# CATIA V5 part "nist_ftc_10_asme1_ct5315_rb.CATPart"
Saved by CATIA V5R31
Part number: nist_ftc_10_asme1
Nomenclature: nist_ftc_10_asme1
Source: Unknown
Bounding box of the stored display mesh (mm): x -79 to 79, y 0 to 31, z -37.5 to 37.5
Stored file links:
  E:\users\dgn\TPS V5\Import-export annotations\Step\PMI representation 2015\NIST UC\FTC\nist_ftc_10_asme1_ct5315_rb.CATPart
  E:\users\dgn\TPS V5\Import-export annotations\Step\PMI representation 2015\NIST UC\FTC\R29\nist_ftc_06_asme1_ct5293_rd.CATPart
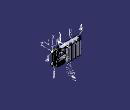
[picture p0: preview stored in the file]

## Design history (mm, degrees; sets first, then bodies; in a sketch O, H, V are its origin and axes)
TTRSSet1
f4a2d38f3ddc11d3a929006094b99c4b_11 "CATTPSSet"
Set1 "MBD_ABCDE"
  AxisSystem1 "ABC": origin (70, 0, 28.5), X (0, 0, 1), Y (-140, 0, 0), Z (0, -1, 0)
Set2 "MBD_B"
  AxisSystem2 "AJ": origin (47.5, 0, 37.5), X (1, 0, 0), Y (0, 1, 0), Z (0, 0, 1)
  Line1: stored without definition
  Line2: type PtDir, RefPoint {point type OnCurve, Support edge [face of Solid1 | face of Solid1], Ratio 0.5}, Direction face of Solid1, Start 15, End 27
  Extract1: ExtractElem face of Solid1
  Extract2: ExtractElem face of Solid1
  Join1: Elements (Extract2; Extract1), ElementsToFederate (face of Solid1; face of Solid1)
  Plane1: type Offset, RefPlane face of Solid1, Offset -2, reversed
  Split1: ToCut Join1, Cutting Plane1
  AxisLine1: Element face of Solid1
  Plane2: type Offset, RefPlane face of Solid1, Offset 0, reversed
  Intersect1: ToIntersect1 AxisLine1, ToIntersect2 Plane2
  AxisSystem3 "DE-F-G": origin (44.5, 27, -25), X (0, 0, -1), Y (-11, 0, 0), Z (0, 1, 0)
  AxisLine2: Element face of Solid1
  Plane3: type Offset, RefPlane face of Solid1, Offset 0, reversed
  Intersect2: ToIntersect1 AxisLine2, ToIntersect2 Plane3
  AxisSystem4 "H": origin (61.7906, 31, 23.5), X (-0.0379, 0, -0.9993), Y (-0.9993, 0, 0.0379), Z (0, 1, 0)
Set3 "MBD_C"
  Extract3: ExtractElem face of Solid1
  Extract4: ExtractElem face of Solid1
  Join2: Elements (Extract3; Extract4), ElementsToFederate (face of Solid1; face of Solid1)
  Split2: ToCut Join2, Cutting Plane1
  AxisSystem5 "DBC": origin (44.5, 27, -25), X (0, 0, -1), Y (-1, 0, 0), Z (0, 1, 0)
  AxisSystem6 "HKL": origin (61.7906, 31, 23.5), X (0, 0, -1), Y (-28.5811, 0, 0), Z (0, 1, 0)
Set4 "MBD_D"
  Sketch1 on face of Solid1, origin (0, 31, 0), H (-1, 0, 0), V (0, 0, 1)
    reference projected arc E1 centre (-52, 23.5) radius 7.5 from (-52, 31) to (-52, 16) ccw from edge [face of Solid1 | face of Solid1]
    point P1 (-52, 31)
    point P2 (-52, 16)
    reference projected arc E2 centre (-43, 23.5) radius 7.5 from (-43, 16) to (-43, 31) ccw from edge [face of Solid1 | face of Solid1]
    point P3 (-43, 16)
    point P4 (-43, 31)
    point P5 (-52.0003, 23.5)
    line L1 (-61.7906, 23.5) -> (-55.4543, 31.0513)
    point P6 (-61.7906, 23.5)
    point P8 (-43, 23.5)
    construction line L2 (-62, 23.5) -> (-31, 23.5)
    line L3 (-61.7906, 23.5) -> (-55.4543, 15.9487)
    point P13 (-33.2094, 23.5)
    line L4 (-33.2094, 23.5) -> (-39.5459, 31.0515)
    line L5 (-33.2094, 23.5) -> (-39.5839, 15.9032)
    radius E1 = 7.5 (reference)
    distance P5 P1 = 7.5
    distance P5 P2 = 7.5
    distance P8 P4 = 7.5
    distance P8 P3 = 7.5
    distance L2 P8 = 0
    angle L1 L3 = 100
    angle L4 L5 = 100
    horizontal: L2 H
    coincidence: P6 L2, P13 L2
    tangency: E1 L1, L3 E1, E2 L4, L5 E2
  Extrude1: Element1 Sketch1, Lim1 7, Lim2 0
  AxisSystem7 "HKL": origin (61.7906, 31, 23.5), X (0, 0, -1), Y (-28.5811, 0, 0), Z (0, 1, 0)
  Extract5: ExtractElem face of Solid1
  Intersect3: ToIntersect1 Extrude1, ToIntersect2 Extract5
  Extract6: ExtractElem face of Solid1
  Intersect4: ToIntersect1 Extract6, ToIntersect2 Extrude1
  AxisSystem8 "DEB": origin (33.5, 27, -25), X (-0.0379, 0, -0.9993), Y (-0.9993, 0, 0.0379), Z (0, 1, 0)
  AxisSystem9 "DFB": origin (44.5, 27, -25), X (-0.0379, 0, -0.9993), Y (-0.9993, 0, 0.0379), Z (0, 1, 0)
  AxisSystem10 "DGB": origin (55.5, 27, -25), X (-0.0379, 0, -0.9993), Y (-0.9993, 0, 0.0379), Z (0, 1, 0)
Body1 "Solid1" (main body)
  Solid1: solid without history
  Sketch2 "Main View" on face of Solid1, origin (62.5, 0, 0), H (0, 0, -1), V (0, 1, 0)
    point P1 (-10.576, 12.74)
    point P2 (-5.1733, 13.2678)
    point P3 (-2.6681, 14.1469)
    point P4 (-0.6107, 14.4183)
    point P5 (-0.1737, 13.9813)
    point P6 (-9.335, 12.74)
    point P7 (-10.576, 12.74)
    point P8 (-9.335, 17.2374)
    point P9 (-9.335, 12.74)
    point P10 (-8.9602, 17.3836)
    point P11 (-9.335, 17.2374)
    point P12 (-5.1733, 13.2678)
    point P13 (-8.9602, 17.3836)
    point P14 (-2.6681, 18.74)
    point P15 (-2.6681, 14.1469)
    point P16 (-3.921, 18.74)
    point P17 (-2.6681, 18.74)
    point P18 (-3.921, 14.1767)
    point P19 (-3.921, 18.74)
    point P20 (-4.208, 14.0503)
    point P21 (-3.921, 14.1767)
    point P22 (-8.3139, 18.4904)
    point P23 (-4.208, 14.0503)
    point P24 (-8.3139, 18.4904)
    point P25 (-10.576, 17.6048)
    point P26 (-10.576, 12.74)
    point P27 (-10.576, 17.6048)
    point P28 (-0.6107, 18.74)
    point P29 (-1.8636, 18.74)
    point P30 (-0.6107, 14.4183)
    point P31 (-0.6107, 18.74)
    point P32 (5.7109, 13.9813)
    point P33 (-0.1737, 13.9813)
    point P34 (5.7109, 13.9813)
    point P35 (5.6879, 15.1078)
    point P36 (2.0672, 15.1078)
    point P37 (5.6879, 15.1078)
    point P38 (1.9296, 18.74)
    point P39 (2.0672, 15.1078)
    point P40 (12.1709, 18.74)
    point P41 (1.9296, 18.74)
    point P42 (12.1709, 17.4756)
    point P43 (12.1709, 18.74)
    point P44 (9.6072, 17.4756)
    point P45 (12.1709, 17.4756)
    point P46 (9.6072, 12.74)
    point P47 (9.6072, 17.4756)
    point P48 (8.3662, 12.74)
    point P49 (9.6072, 12.74)
    point P50 (8.3662, 17.4756)
    point P51 (8.3662, 12.74)
    point P52 (2.0902, 17.4756)
    point P53 (8.3662, 17.4756)
    point P54 (2.0902, 17.4756)
    point P55 (2.0442, 16.3492)
    point P56 (5.8949, 16.3492)
    point P57 (2.0442, 16.3492)
    point P58 (5.8949, 12.74)
    point P59 (5.8949, 16.3492)
    point P60 (-0.1853, 12.74)
    point P61 (5.8949, 12.74)
    point P62 (-1.8636, 14.4183)
    point P63 (-0.1853, 12.74)
    point P64 (-1.8636, 18.74)
    point P65 (-1.8636, 14.4183)
    line L1 (-1.8636, 18.74) -> (-1.8636, 14.4183)
    arc A1 centre (-0.1853, 14.4183) radius 1.6783 from (-1.8636, 14.4183) to (-0.1853, 12.74) ccw
    line L2 (-0.1853, 12.74) -> (5.8949, 12.74)
    arc A2 centre (5.6075, 14.5446) radius 1.8273 from (5.8949, 12.74) to (5.8949, 16.3492) ccw
    line L3 (5.8949, 16.3492) -> (2.0442, 16.3492)
    arc A3 centre (2.0442, 16.9133) radius 0.5642 from (2.0902, 17.4756) to (2.0442, 16.3492) ccw
    line L4 (2.0902, 17.4756) -> (8.3662, 17.4756)
    line L5 (8.3662, 17.4756) -> (8.3662, 12.74)
    line L6 (8.3662, 12.74) -> (9.6072, 12.74)
    line L7 (9.6072, 12.74) -> (9.6072, 17.4756)
    line L8 (9.6072, 17.4756) -> (12.1709, 17.4756)
    line L9 (12.1709, 17.4756) -> (12.1709, 18.74)
    line L10 (12.1709, 18.74) -> (1.9296, 18.74)
    arc A4 centre (1.9296, 16.9213) radius 1.8187 from (1.9296, 18.74) to (2.0672, 15.1078) ccw
    line L11 (2.0672, 15.1078) -> (5.6879, 15.1078)
    arc A5 centre (5.6389, 14.5433) radius 0.5666 from (5.7109, 13.9813) to (5.6879, 15.1078) ccw
    line L12 (5.7109, 13.9813) -> (-0.1737, 13.9813)
    line L13 (-0.6107, 14.4183) -> (-0.6107, 18.74)
    line L14 (-0.6107, 18.74) -> (-1.8636, 18.74)
    line L15 (-10.576, 12.74) -> (-10.576, 17.6048)
    arc A6 centre (-9.2716, 17.6048) radius 1.3044 from (-8.3139, 18.4904) to (-10.576, 17.6048) ccw
    line L16 (-8.3139, 18.4904) -> (-4.208, 14.0503)
    arc A7 centre (-4.0862, 14.1629) radius 0.1659 from (-4.208, 14.0503) to (-3.921, 14.1767) ccw
    line L17 (-3.921, 14.1767) -> (-3.921, 18.74)
    line L18 (-3.921, 18.74) -> (-2.6681, 18.74)
    line L19 (-2.6681, 18.74) -> (-2.6681, 14.1469)
    line L20 (-5.1733, 13.2678) -> (-8.9602, 17.3836)
    arc A8 centre (-9.1191, 17.2374) radius 0.2159 from (-8.9602, 17.3836) to (-9.335, 17.2374) ccw
    line L21 (-9.335, 17.2374) -> (-9.335, 12.74)
    line L22 (-9.335, 12.74) -> (-10.576, 12.74)
    arc A9 centre (-0.1737, 14.4183) radius 0.437 from (-0.6107, 14.4183) to (-0.1737, 13.9813) ccw
    arc A10 centre (-4.0749, 14.1469) radius 1.4069 from (-5.1733, 13.2678) to (-2.6681, 14.1469) ccw
    distance P1 H = 12.74
    distance P1 V = 10.576
    coincidence: P2 P12, P3 P15, P4 P30, P5 P33, P6 P9, P7 P26, P8 P11, P10 P13, P14 P17, P16 P19, P18 P21, P20 P23, P22 P24, P25 P27, P28 P31, P29 P64, P32 P34, P35 P37, P36 P39, P38 P41, P40 P43, P42 P45, P44 P47, P46 P49, P48 P51, P50 P53, P52 P54, P55 P57, P56 P59, P58 P61, P60 P63, P62 P65
  Pocket1: profile Sketch2, direction (-1, 0, 0), length 2.54
  Join3: Elements (face of Solid1; face of Solid1), ElementsToFederate (face of Solid1; face of Solid1)
  SewSurface1: SplitPlane Join3
  Join4: Elements (face of Solid1; face of Solid1), ElementsToFederate (face of Solid1; face of Solid1)
  SewSurface2: SplitPlane Join4
  Thread1: "M3", diameter 3, depth 10, pitch 0.5, on face of SewSurface1, from face of Solid1
  Thread2: "M3", diameter 3, depth 10, pitch 0.5, on face of SewSurface2, from face of Solid1
  Join5: Elements (face of Solid1; face of Solid1), ElementsToFederate (face of Solid1; face of Solid1)
  Join6: Elements (face of Solid1; face of Solid1), ElementsToFederate (face of Solid1; face of Solid1)
  SewSurface3: SplitPlane Join5
  SewSurface4: SplitPlane Join6
  Thread3: "M3", diameter 3, depth 10, pitch 0.5, on face of SewSurface4, from face of Solid1
  Thread4: "M3", diameter 3, depth 10, pitch 0.5, on face of SewSurface3, from face of Solid1
  Join7: Elements (face of Solid1; face of Solid1), ElementsToFederate (face of Solid1; face of Solid1)
  Join8: Elements (face of Solid1; face of Solid1), ElementsToFederate (face of Solid1; face of Solid1)
  SewSurface5: SplitPlane Join7
  SewSurface6: SplitPlane Join8
  Thread5: "M3", diameter 3, depth 10, pitch 0.5, on face of SewSurface5, from face of Solid1
  Thread6: "M3", diameter 3, depth 10, pitch 0.5, on face of SewSurface6, from face of Solid1
  Fillet1: radius 0.15, on edge [face of Solid1 | face of Solid1] (x4)
  Fillet2: radius 0.2, on edge [face of Solid1 | face of Solid1] (x4)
